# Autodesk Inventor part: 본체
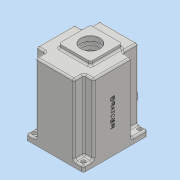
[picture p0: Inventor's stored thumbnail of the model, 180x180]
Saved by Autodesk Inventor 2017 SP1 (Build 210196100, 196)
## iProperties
Part Number: 본체
Material: 일반
Document SubType Name: Modeling
Designer: MRC
Density: 1 g/cm^3
Appearance: 기본값
Author: MRC
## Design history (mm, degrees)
sketch "스케치1"
  geometry: L1 (-49, -55)-(49, 55); L2 (49, -55)-(-49, 55); L3 (49, 55)-(33, 55); L4 (33, 55)-(33, 28); L5 (33, 28)-(49, 28); L6 (49, 28)-(49, 55); L7 (49, -55)-(33, -55); L8 (33, -55)-(33, -38); L9 (33, -38)-(49, -38); L10 (49, -38)-(49, -55); L11 (-49, -55)-(-33, -55); L12 (-33, -55)-(-33, -38); L13 (-33, -38)-(-49, -38); L14 (-49, -38)-(-49, -55); L15 (-49, 55)-(-33, 55); L16 (-33, 55)-(-33, 28); L17 (-33, 28)-(-49, 28); L18 (-49, 28)-(-49, 55); L19 (-49, 28)-(-49, -38); L20 (49, 28)-(49, -38); L21 (-33, 55)-(33, 55); L22 (-33, -55)-(33, -55); 1 further point
  constraints: 44 end point, 8 parallel, 4 horizontal, 4 perpendicular, 2 collinear, 2 midpoint, 2 vertical, 1 point on line
  dimensions: "d0" = 98 distance of L2.end L1.end; "d1" = 110 distance of L1.end L2.start; "d2" = 16 distance of L5.end L4.end; "d3" = 27 distance of L3.end L4.end; "d4" = 16 distance of L8.end L9.end; "d5" = 17 distance of L7.end L8.end; "d6" = 16 distance of L13.end L12.end; "d7" = 17 distance of L12.end L11.end; "d8" = 16 distance of L16.end L17.end; "d9" = 27 distance of L15.end L16.end; "d10" = 41.6981 deg angle of L10 L1
extrude "돌출1" new body sketch "스케치1" stored distance "d11" = 130; taper "d12" = 0 deg
sketch "스케치2"
  geometry: L1 (-33, 55)-(-33, 28) reference; L2 (-33, 28)-(-49, 28) reference; L3 (-49, 28)-(-49, -38) reference; L4 (-49, -38)-(-33, -38) reference; L5 (-33, -38)-(-33, -55) reference; L6 (-33, -55)-(33, -55) reference; L7 (33, -55)-(33, -38) reference; L8 (33, -38)-(49, -38) reference; L9 (49, -38)-(49, 28) reference; L10 (49, 28)-(33, 28) reference; L11 (33, 28)-(33, 55) reference; L12 (33, 55)-(-33, 55) reference; L13 (-49, -55)-(49, -55); L14 (49, -55)-(49, 55); L15 (49, 55)-(-49, 55); L16 (-49, 55)-(-49, -55); L17 (-49, -55)-(49, 55); L18 (49, -55)-(-49, 55); 1 further point
  constraints: 12 end point, 2 midpoint, 2 parallel, 1 horizontal, 1 perpendicular
  dimensions: "d13" = 98 distance of L14.end L15.end; "d14" = 110 distance of L13.end L14.end
extrude "돌출2" join sketch "스케치2" distance "d15" = 10; taper "d16" = 0 deg
sketch "스케치3"
  geometry: L1 (-27, 33)-(27, 33); L2 (27, 33)-(27, -21); L3 (27, -21)-(-27, -21); L4 (-27, -21)-(-27, 33); L5 (-27, 33)-(27, -21); L6 (27, 33)-(-27, -21); L7 (-33, -55)-(33, -55) reference; 3 further points
  constraints: 12 end point, 3 midpoint, 2 parallel, 1 horizontal, 1 perpendicular, 1 vertical alignment
  dimensions: "d18" = 54 distance of L1.start L1.end; "d19" = 54 distance of L1.end L2.end; "d46" = 61 distance from line of L7 point (0, 6)
extrude "돌출3" join sketch "스케치3" distance "d20" = 7; taper "d21" = 0 deg
sketch "스케치5"
  geometry: L1 (27, 33)-(-27, 33) reference; L2 (27, 33)-(-27, 33) reference; L3 (-27, 33)-(-27, -21) reference; L4 (-27, -21)-(27, -21) reference; L5 (27, -21)-(27, 33) reference; C1 r 16 at (0, 6); 1 further point
  constraints: 1 centre point, 1 vertical alignment
  dimensions: "d22" = 32 diameter of C1; "d23" = 27 distance from line of C1.centre L1
extrude "돌출4" cut sketch "스케치5" distance "d24" = 8.3; taper "d25" = 0 deg
sketch "스케치6"
  geometry: L1 (49, 55)-(-49, 55) reference; L2 (-49, -55)-(49, -55) reference; L3 (49, -55)-(49, 55) reference; L4 (-26, 48)-(26, 48); L5 (26, 48)-(26, 31.729); L6 (-26, 31.729)-(-26, 48); A1 r 45 centre (0, -5) between (-26, 31.729) and (26, 31.729); 2 further points
  constraints: 6 end point, 2 point on circle, 2 vertical alignment, 1 centre point, 1 horizontal, 1 parallel, 1 perpendicular
  dimensions: "d28" = 90 diameter of A1; "d29" = 50 distance from line of L2 A1.centre; "d30" = 53 distance from line of A1.centre L4; "d31" = 52 distance between parallel lines of L5 L6; "d32" = 23 distance between parallel lines of L3 L5; "d33" = 25.02005 distance from line of point (0, 29.98) L1
extrude "돌출5" cut sketch "스케치6" distance "d34" = 9; taper "d35" = 0 deg
sketch "스케치7"
  geometry: L1 (-26, 48)-(26, 48) reference; L2 (-26, 31.729)-(-26, 48) reference; L3 (26, 48)-(26, 31.729) reference; L4 (-23, 30.143)-(-23, 45); L5 (-23, 45)-(23, 45); L6 (23, 45)-(23, 30.143); A1 r 45 centre (0, -5) between (-26, 31.729) and (26, 31.729) reference; A2 r 42 centre (0, -5) between (-23, 30.143) and (23, 30.143); 1 further point
  constraints: 6 end point, 2 point on circle, 1 centre point, 3 other
  dimensions: "d36" = 3 radial gap between concentric circles of A1 A2
fillet "모깎기1" dims "d37" = 3
extrude "돌출6" cut sketch "스케치7" distance "d38" = 112; taper "d39" = 0 deg
sketch "스케치8"
  geometry: C1 r 21 at (0, 6); C2 r 15 at (0, -25); A1 r 42 centre (0, -5) between (-23, 30.143) and (23, 30.143) reference; 1 further point
  constraints: 2 centre point, 2 vertical alignment
  dimensions: "d40" = 42 diameter of C1; "d41" = 30 diameter of C2; "d42" = 20 distance of C2.centre A1.centre; "d43" = 11 distance of C1.centre A1.centre
extrude "돌출7" join sketch "스케치8" distance "d44" = 7; taper "d45" = 0 deg
sketch "스케치9"
  geometry: C1 r 17.5 at (0, 6); A1 r 21 centre (0, 6) between (8.978, -12.984) and (-8.978, -12.984) reference; 1 further point
  constraints: 1 centre point, 1 coincident
  dimensions: "d47" = 35 diameter of C1
extrude "돌출8" cut sketch "스케치9" distance "d48" = 10; taper "d49" = 0 deg
sketch "스케치10"
  geometry: C1 r 17.5 at (0, 0) reference; C2 r 14 at (0, 0); 1 further point
  constraints: 1 centre point, 1 coincident
  dimensions: "d50" = 28 diameter of C2
extrude "돌출9" cut sketch "스케치10" stored distance "d51" = 10; taper "d52" = 0 deg
sketch "스케치11"
  geometry: A1 r 15 centre (0, -25) between (-8.978, -12.984) and (8.978, -12.984) reference; 2 further points
  constraints: 1 coincident
hole "구멍1" sketch "스케치11" at (0, -25) diameter "d53" = 19; stored, may be unused: countersink angle "d57" = 90 deg, drill point angle "d59" = 0 deg; dims "d54" = 6, "d55" = 22, "d56" = 7, "d58" = 10
fillet "모깎기2" dims "d60" = 3
sketch "스케치12" dims "d61" = 72
  geometry: L1 (-36, -1)-(-41.809, -1); L2 (-36, -9)-(-41.809, -9); A1 r 42 centre (0, -5) between (-23, 30.143) and (23, 30.143) reference; A2 r 45 centre (0, -5) between (-26, 31.729) and (26, 31.729) reference; A3 r 4 centre (-36, -5) between (-36, -9) and (-36, -1); 2 further points
  constraints: 4 end point, 4 point on circle, 2 horizontal, 2 horizontal alignment, 2 tangent, 1 centre point, 1 coincident, 3 other
  dimensions: "d62" = 8 diameter of A3
extrude "돌출10" join sketch "스케치12" stored distance "d63" = 10; taper "d64" = 0 deg
sketch "스케치13"
  geometry: A1 r 4 centre (-36, -5) between (-36, -9) and (-36, -1) reference; 2 further points
  constraints: 1 coincident
hole "구멍2" sketch "스케치13" at (-36, -5) diameter "d65" = 3.242; stored, may be unused: countersink angle "d69" = 90 deg, drill point angle "d71" = 118 deg; dims "d66" = 7, "d67" = 22, "d68" = 7, "d70" = 9
fillet "모깎기3" dims "d72" = 3
fillet "모깎기18" dims "d130" = 6
fillet "모깎기4" dims "d73" = 3
fillet "모깎기5" dims "d74" = 3
sketch "스케치14"
  geometry: L1 (0, 0)-(98, 0) reference; C1 r 22.5 at (49, -40); C2 r 15 at (49, -89); 1 further point
  constraints: 2 centre point, 2 vertical alignment
  dimensions: "d75" = 40 distance from line of L1 C1.centre; "d76" = 49 distance of C1.centre C2.centre; "d77" = 45 diameter of C1; "d78" = 30 diameter of C2
extrude "돌출11" join sketch "스케치14" distance "d79" = 10; taper "d80" = 0 deg
extrude "돌출12" join sketch "스케치14" distance "d81" = 5; taper "d82" = 0 deg
hole "구멍3" diameter "d85" = 33.376; stored, may be unused: countersink angle "d89" = 90 deg, drill point angle "d91" = 118 deg; dims "d83" = 10, "d84" = 10, "d86" = 70, "d87" = 22, "d88" = 7, "d90" = 77.3
sketch "스케치17"
  geometry: C1 r 10 at (0, 0); 2 further points
  constraints: 1 centre point, 1 coincident, 1 vertical alignment
  dimensions: "d92" = 20 diameter of C1
extrude "돌출13" cut sketch "스케치17" stored distance "d93" = 5; taper "d94" = 0 deg
sketch "스케치18"
  geometry: C1 r 10 at (20, 80) reference; C2 r 15 at (20, 80); 1 further point
  constraints: 1 centre point, 1 coincident
  dimensions: "d95" = 30 diameter of C2
extrude "돌출14" cut sketch "스케치18" distance "d96" = 5; taper "d97" = 0 deg
sketch "스케치19"
  geometry: L1 (49, 28)-(49, 55) reference; L2 (49, 55)-(33, 55) reference; L3 (-49, 55)-(-49, 28) reference; L4 (-49, -55)-(-33, -55) reference; 5 further points
  constraints: 2 horizontal alignment, 2 vertical alignment
  dimensions: "d98" = 7 distance from line of L2 point (42, 48); "d99" = 7 distance from line of L1 point (42, 48); "d100" = 7 distance from line of L3 point (-42, 48); "d101" = 7 distance from line of L4 point (-42, -48)
hole "구멍4" sketch "스케치19" at (42, 48), (-42, 48), (-42, -48), (42, -48) diameter "d102" = 7; stored, may be unused: countersink angle "d106" = 90 deg, drill point angle "d108" = 0 deg; dims "d103" = 70, "d104" = 22, "d105" = 7, "d107" = 77.3
fillet "모깎기6" dims "d109" = 3
fillet "모깎기7" dims "d110" = 3
fillet "모깎기8" dims "d111" = 3
fillet "모깎기9" dims "d112" = 3
fillet "모깎기10" dims "d113" = 3
fillet "모깎기11" dims "d114" = 3
fillet "모깎기12" dims "d115" = 3
fillet "모깎기13" dims "d116" = 3
chamfer "모따기1" distance "d117" = 0.8; stored, may be unused: second distance "d118" = 2, angle "d119" = 30 deg
fillet "모깎기14" dims "d120" = 0.3
chamfer "모따기2" distance "d121" = 1; stored, may be unused: second distance "d122" = 2, angle "d123" = 30 deg
fillet "모깎기15" dims "d124" = 3
chamfer "모따기3" distance "d125" = 1; stored, may be unused: second distance "d126" = 2, angle "d127" = 30 deg
fillet "모깎기16" dims "d128" = 3
fillet "모깎기17" dims "d129" = 3
sketch "스케치20"
  geometry: L1 (-13, 80)-(-127, 80) reference; L2 (-130, 104)-(-130, 83) reference; 2 further points
  constraints: 1 other
  dimensions: "d131" = 33 distance from line of point (-65, 47) L1; "d132" = 65 distance from line of point (-65, 47) L2
feature "엠보싱1" sketch "스케치20" dims "d0" = 98, "d1" = 110, "d2" = 16, "d3" = 27, "d4" = 16, "d5" = 17, "d6" = 16, "d7" = 17, "d8" = 16, "d9" = 27, "d10" = 7.2777, "d133" = 0.5, "d134" = 0
chamfer "모따기4" distance "d135" = 1; stored, may be unused: second distance "d136" = 2, angle "d137" = 30 deg
node "솔리드1"
mirror "미러1"
node "투영된 루프1"
